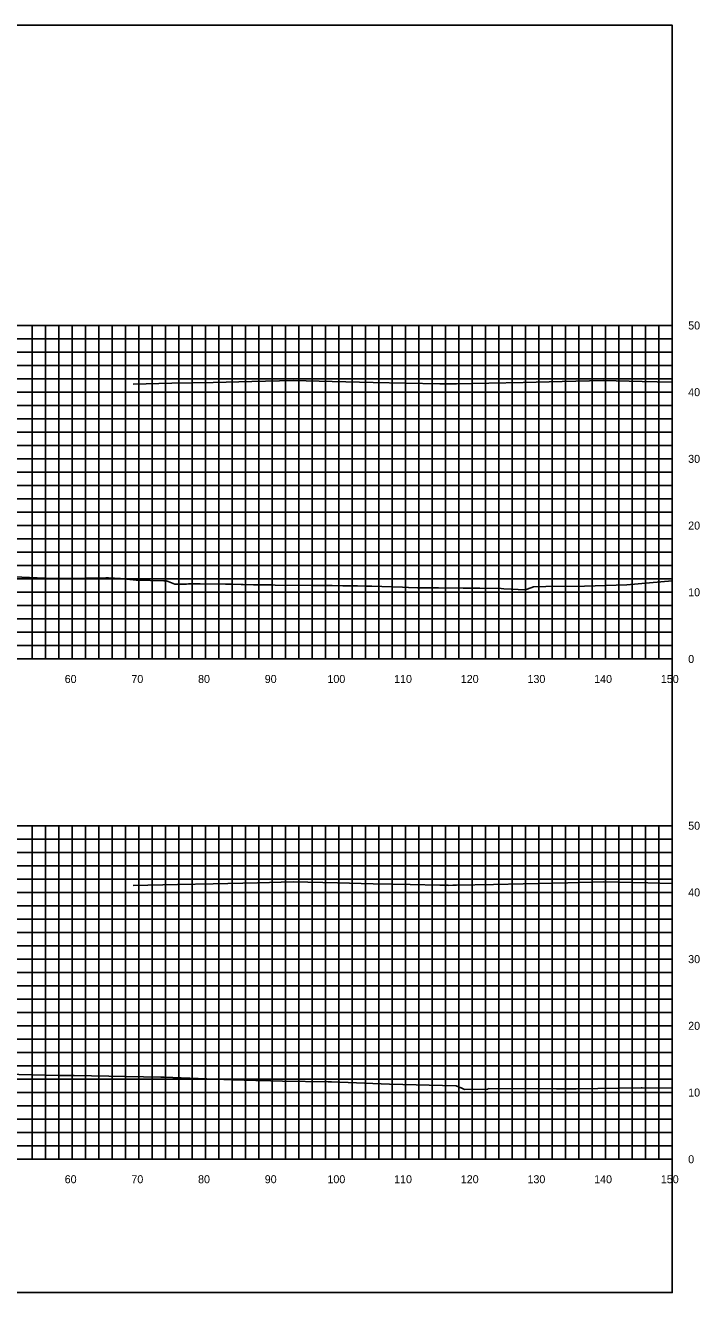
# Model space of a CAD drawing. Extents: x 1797714 to 1804825, y 249015 to 250269.
# Drawn here: x 1802997.2 to 1803098.3, y 249628.2 to 249818.2 of the extents above; entities that cross this region are included whole.
import ezdxf

# ---------------------------------------------------------------- set-up
doc = ezdxf.new("R2010")
doc.units = 0
for name, color, linetype in [('10', 7, 'Continuous'), ('31', 7, 'Continuous'), ('60', 7, 'Continuous'), ('CL-CNST', 7, 'Continuous'), ('Level 62', 7, 'Continuous'), ('M-ROADS', 7, 'Continuous')]:
    doc.layers.add(name, color=color, linetype=linetype)

msp = doc.modelspace()

# ---------------------------------------------------------------- linework, layer by layer
msp.add_lwpolyline([(1802794.16, 249628.17), (1803094.16, 249628.17), (1803094.16, 249818.17), (1802794.16, 249818.17)], close=True)
at = {"layer": '60'}
for p, q in [((1803094.16, 249723.17), (1803094.16, 249773.17)), ((1803094.22, 249773.17), (1803094.16, 249773.17)), ((1803094.22, 249763.17), (1803094.16, 249763.17)), ((1803094.22, 249753.17), (1803094.16, 249753.17)), ((1803094.22, 249743.17), (1803094.16, 249743.17)), ((1803094.22, 249733.17), (1803094.16, 249733.17)), ((1802794.16, 249723.17), (1803094.16, 249723.17)), ((1803004.16, 249723.11), (1803004.16, 249723.17)), ((1803014.16, 249723.11), (1803014.16, 249723.17)), ((1803024.16, 249723.11), (1803024.16, 249723.17)), ((1803034.16, 249723.11), (1803034.16, 249723.17)), ((1803044.16, 249723.11), (1803044.16, 249723.17)), ((1803054.16, 249723.11), (1803054.16, 249723.17)), ((1803064.16, 249723.11), (1803064.16, 249723.17)), ((1803074.16, 249723.11), (1803074.16, 249723.17)), ((1803084.16, 249723.11), (1803084.16, 249723.17)), ((1803094.16, 249723.11), (1803094.16, 249723.17)), ((1803094.22, 249723.17), (1803094.16, 249723.17)), ((1803094.16, 249648.17), (1803094.16, 249698.17)), ((1803094.22, 249698.17), (1803094.16, 249698.17)), ((1803094.22, 249688.17), (1803094.16, 249688.17)), ((1803094.22, 249678.17), (1803094.16, 249678.17)), ((1803094.22, 249668.17), (1803094.16, 249668.17)), ((1803094.22, 249658.17), (1803094.16, 249658.17)), ((1802794.16, 249648.17), (1803094.16, 249648.17)), ((1803004.16, 249648.11), (1803004.16, 249648.17)), ((1803014.16, 249648.11), (1803014.16, 249648.17)), ((1803024.16, 249648.11), (1803024.16, 249648.17)), ((1803034.16, 249648.11), (1803034.16, 249648.17)), ((1803044.16, 249648.11), (1803044.16, 249648.17)), ((1803054.16, 249648.11), (1803054.16, 249648.17)), ((1803064.16, 249648.11), (1803064.16, 249648.17)), ((1803074.16, 249648.11), (1803074.16, 249648.17)), ((1803084.16, 249648.11), (1803084.16, 249648.17)), ((1803094.16, 249648.11), (1803094.16, 249648.17)), ((1803094.22, 249648.17), (1803094.16, 249648.17))]:
    msp.add_line(p, q, dxfattribs=at)
at = {"layer": 'CL-CNST'}
for points in [[(1803013.32, 249764.38), (1803019.14, 249764.51), (1803025.32, 249764.64), (1803031.14, 249764.77), (1803037.32, 249764.91), (1803043.15, 249764.78), (1803049.32, 249764.64), (1803054.18, 249764.54), (1803059.32, 249764.42), (1803059.92, 249764.41), (1803060.57, 249764.4), (1803060.57, 249764.4), (1803060.57, 249764.4), (1803061.18, 249764.41), (1803061.82, 249764.42), (1803066.68, 249764.53), (1803071.82, 249764.64), (1803077.65, 249764.77), (1803083.82, 249764.91), (1803089.66, 249764.78), (1803094.16, 249764.68)], [(1803013.33, 249689.22), (1803019.98, 249689.36), (1803025.33, 249689.48), (1803031.99, 249689.63), (1803037.33, 249689.75), (1803043.99, 249689.6), (1803049.33, 249689.48), (1803054.88, 249689.36), (1803059.33, 249689.26), (1803060.02, 249689.25), (1803060.58, 249689.24), (1803060.58, 249689.23), (1803060.58, 249689.23), (1803061.27, 249689.25), (1803061.83, 249689.26), (1803067.38, 249689.38), (1803071.83, 249689.48), (1803078.5, 249689.63), (1803083.83, 249689.75), (1803090.5, 249689.6), (1803094.16, 249689.52)]]:
    msp.add_lwpolyline(points, dxfattribs=at)
at = {"layer": 'Level 62'}
for p, q in [((1802794.16, 249773.17), (1803094.16, 249773.17)), ((1802998.16, 249723.17), (1802998.16, 249773.17)), ((1803000.16, 249723.17), (1803000.16, 249773.17)), ((1803002.16, 249723.17), (1803002.16, 249773.17)), ((1803004.16, 249723.17), (1803004.16, 249773.17)), ((1803006.16, 249723.17), (1803006.16, 249773.17)), ((1803008.16, 249723.17), (1803008.16, 249773.17)), ((1803010.16, 249723.17), (1803010.16, 249773.17)), ((1803012.16, 249723.17), (1803012.16, 249773.17)), ((1803014.16, 249723.17), (1803014.16, 249773.17)), ((1803016.16, 249723.17), (1803016.16, 249773.17)), ((1803018.16, 249723.17), (1803018.16, 249773.17)), ((1803020.16, 249723.17), (1803020.16, 249773.17)), ((1803022.16, 249723.17), (1803022.16, 249773.17)), ((1803024.16, 249723.17), (1803024.16, 249773.17)), ((1803026.16, 249723.17), (1803026.16, 249773.17)), ((1803028.16, 249723.17), (1803028.16, 249773.17)), ((1803030.16, 249723.17), (1803030.16, 249773.17)), ((1803032.16, 249723.17), (1803032.16, 249773.17)), ((1803034.16, 249723.17), (1803034.16, 249773.17)), ((1803036.16, 249723.17), (1803036.16, 249773.17)), ((1803038.16, 249723.17), (1803038.16, 249773.17)), ((1803040.16, 249723.17), (1803040.16, 249773.17)), ((1803042.16, 249723.17), (1803042.16, 249773.17)), ((1803044.16, 249723.17), (1803044.16, 249773.17)), ((1803046.16, 249723.17), (1803046.16, 249773.17)), ((1803048.16, 249723.17), (1803048.16, 249773.17)), ((1803050.16, 249723.17), (1803050.16, 249773.17)), ((1803052.16, 249723.17), (1803052.16, 249773.17)), ((1803054.16, 249723.17), (1803054.16, 249773.17)), ((1803056.16, 249723.17), (1803056.16, 249773.17)), ((1803058.16, 249723.17), (1803058.16, 249773.17)), ((1803060.16, 249723.17), (1803060.16, 249773.17)), ((1803062.16, 249723.17), (1803062.16, 249773.17)), ((1803064.16, 249723.17), (1803064.16, 249773.17)), ((1803066.16, 249723.17), (1803066.16, 249773.17)), ((1803068.16, 249723.17), (1803068.16, 249773.17)), ((1803070.16, 249723.17), (1803070.16, 249773.17)), ((1803072.16, 249723.17), (1803072.16, 249773.17)), ((1803074.16, 249723.17), (1803074.16, 249773.17)), ((1803076.16, 249723.17), (1803076.16, 249773.17)), ((1803078.16, 249723.17), (1803078.16, 249773.17)), ((1803080.16, 249723.17), (1803080.16, 249773.17)), ((1803082.16, 249723.17), (1803082.16, 249773.17)), ((1803084.16, 249723.17), (1803084.16, 249773.17)), ((1803086.16, 249723.17), (1803086.16, 249773.17)), ((1803088.16, 249723.17), (1803088.16, 249773.17)), ((1803090.16, 249723.17), (1803090.16, 249773.17)), ((1803092.16, 249723.17), (1803092.16, 249773.17)), ((1803094.16, 249723.17), (1803094.16, 249773.17)), ((1802794.16, 249771.17), (1803094.16, 249771.17)), ((1802794.16, 249769.17), (1803094.16, 249769.17)), ((1802794.16, 249767.17), (1803094.16, 249767.17)), ((1802794.16, 249765.17), (1803094.16, 249765.17)), ((1802794.16, 249763.17), (1803094.16, 249763.17)), ((1802794.16, 249761.17), (1803094.16, 249761.17)), ((1802794.16, 249759.17), (1803094.16, 249759.17)), ((1802794.16, 249757.17), (1803094.16, 249757.17)), ((1802794.16, 249755.17), (1803094.16, 249755.17)), ((1802794.16, 249753.17), (1803094.16, 249753.17)), ((1802794.16, 249751.17), (1803094.16, 249751.17)), ((1802794.16, 249749.17), (1803094.16, 249749.17)), ((1802794.16, 249747.17), (1803094.16, 249747.17)), ((1802794.16, 249745.17), (1803094.16, 249745.17)), ((1802794.16, 249743.17), (1803094.16, 249743.17)), ((1802794.16, 249741.17), (1803094.16, 249741.17)), ((1802794.16, 249739.17), (1803094.16, 249739.17)), ((1802794.16, 249737.17), (1803094.16, 249737.17)), ((1802794.16, 249735.17), (1803094.16, 249735.17)), ((1802794.16, 249733.17), (1803094.16, 249733.17)), ((1802794.16, 249731.17), (1803094.16, 249731.17)), ((1802794.16, 249729.17), (1803094.16, 249729.17)), ((1802794.16, 249727.17), (1803094.16, 249727.17)), ((1802794.16, 249725.17), (1803094.16, 249725.17)), ((1802794.16, 249723.17), (1803094.16, 249723.17)), ((1802794.16, 249698.17), (1803094.16, 249698.17)), ((1802998.16, 249648.17), (1802998.16, 249698.17)), ((1803000.16, 249648.17), (1803000.16, 249698.17)), ((1803002.16, 249648.17), (1803002.16, 249698.17)), ((1803004.16, 249648.17), (1803004.16, 249698.17)), ((1803006.16, 249648.17), (1803006.16, 249698.17)), ((1803008.16, 249648.17), (1803008.16, 249698.17)), ((1803010.16, 249648.17), (1803010.16, 249698.17)), ((1803012.16, 249648.17), (1803012.16, 249698.17)), ((1803014.16, 249648.17), (1803014.16, 249698.17)), ((1803016.16, 249648.17), (1803016.16, 249698.17)), ((1803018.16, 249648.17), (1803018.16, 249698.17)), ((1803020.16, 249648.17), (1803020.16, 249698.17)), ((1803022.16, 249648.17), (1803022.16, 249698.17)), ((1803024.16, 249648.17), (1803024.16, 249698.17)), ((1803026.16, 249648.17), (1803026.16, 249698.17)), ((1803028.16, 249648.17), (1803028.16, 249698.17)), ((1803030.16, 249648.17), (1803030.16, 249698.17)), ((1803032.16, 249648.17), (1803032.16, 249698.17)), ((1803034.16, 249648.17), (1803034.16, 249698.17)), ((1803036.16, 249648.17), (1803036.16, 249698.17)), ((1803038.16, 249648.17), (1803038.16, 249698.17)), ((1803040.16, 249648.17), (1803040.16, 249698.17)), ((1803042.16, 249648.17), (1803042.16, 249698.17)), ((1803044.16, 249648.17), (1803044.16, 249698.17)), ((1803046.16, 249648.17), (1803046.16, 249698.17)), ((1803048.16, 249648.17), (1803048.16, 249698.17)), ((1803050.16, 249648.17), (1803050.16, 249698.17)), ((1803052.16, 249648.17), (1803052.16, 249698.17)), ((1803054.16, 249648.17), (1803054.16, 249698.17)), ((1803056.16, 249648.17), (1803056.16, 249698.17)), ((1803058.16, 249648.17), (1803058.16, 249698.17)), ((1803060.16, 249648.17), (1803060.16, 249698.17)), ((1803062.16, 249648.17), (1803062.16, 249698.17)), ((1803064.16, 249648.17), (1803064.16, 249698.17)), ((1803066.16, 249648.17), (1803066.16, 249698.17)), ((1803068.16, 249648.17), (1803068.16, 249698.17)), ((1803070.16, 249648.17), (1803070.16, 249698.17)), ((1803072.16, 249648.17), (1803072.16, 249698.17)), ((1803074.16, 249648.17), (1803074.16, 249698.17)), ((1803076.16, 249648.17), (1803076.16, 249698.17)), ((1803078.16, 249648.17), (1803078.16, 249698.17)), ((1803080.16, 249648.17), (1803080.16, 249698.17)), ((1803082.16, 249648.17), (1803082.16, 249698.17)), ((1803084.16, 249648.17), (1803084.16, 249698.17)), ((1803086.16, 249648.17), (1803086.16, 249698.17)), ((1803088.16, 249648.17), (1803088.16, 249698.17)), ((1803090.16, 249648.17), (1803090.16, 249698.17)), ((1803092.16, 249648.17), (1803092.16, 249698.17)), ((1803094.16, 249648.17), (1803094.16, 249698.17)), ((1802794.16, 249696.17), (1803094.16, 249696.17)), ((1802794.16, 249694.17), (1803094.16, 249694.17)), ((1802794.16, 249692.17), (1803094.16, 249692.17)), ((1802794.16, 249690.17), (1803094.16, 249690.17)), ((1802794.16, 249688.17), (1803094.16, 249688.17)), ((1802794.16, 249686.17), (1803094.16, 249686.17)), ((1802794.16, 249684.17), (1803094.16, 249684.17)), ((1802794.16, 249682.17), (1803094.16, 249682.17)), ((1802794.16, 249680.17), (1803094.16, 249680.17)), ((1802794.16, 249678.17), (1803094.16, 249678.17)), ((1802794.16, 249676.17), (1803094.16, 249676.17)), ((1802794.16, 249674.17), (1803094.16, 249674.17)), ((1802794.16, 249672.17), (1803094.16, 249672.17)), ((1802794.16, 249670.17), (1803094.16, 249670.17)), ((1802794.16, 249668.17), (1803094.16, 249668.17)), ((1802794.16, 249666.17), (1803094.16, 249666.17)), ((1802794.16, 249664.17), (1803094.16, 249664.17)), ((1802794.16, 249662.17), (1803094.16, 249662.17)), ((1802794.16, 249660.17), (1803094.16, 249660.17)), ((1802794.16, 249658.17), (1803094.16, 249658.17)), ((1802794.16, 249656.17), (1803094.16, 249656.17)), ((1802794.16, 249654.17), (1803094.16, 249654.17)), ((1802794.16, 249652.17), (1803094.16, 249652.17)), ((1802794.16, 249650.17), (1803094.16, 249650.17)), ((1802794.16, 249648.17), (1803094.16, 249648.17))]:
    msp.add_line(p, q, dxfattribs=at)
at = {"layer": 'M-ROADS'}
for points in [[(1802987.34, 249735.85), (1803000.09, 249735.31), (1803002.32, 249735.22), (1803002.57, 249735.22), (1803002.57, 249735.22), (1803002.82, 249735.22), (1803003.42, 249735.22), (1803009.24, 249735.33), (1803009.63, 249735.33), (1803011.44, 249735.26), (1803013.8, 249734.99), (1803013.88, 249734.99), (1803017.91, 249734.9), (1803018.04, 249734.9), (1803018.24, 249734.89), (1803018.29, 249734.88), (1803018.44, 249734.84), (1803018.56, 249734.79), (1803019.57, 249734.37), (1803020.62, 249734.39), (1803020.72, 249734.39), (1803020.83, 249734.4), (1803020.97, 249734.4), (1803021.14, 249734.4), (1803021.35, 249734.41), (1803021.63, 249734.42), (1803022.02, 249734.43), (1803022.54, 249734.44), (1803023.26, 249734.46), (1803023.28, 249734.46), (1803023.31, 249734.46), (1803023.32, 249734.46), (1803023.38, 249734.46), (1803027.16, 249734.4), (1803028.06, 249734.38), (1803029.51, 249734.35), (1803029.82, 249734.34), (1803031.35, 249734.31), (1803032.41, 249734.29), (1803033.2, 249734.28), (1803033.51, 249734.28), (1803034.14, 249734.27), (1803034.64, 249734.26), (1803040.01, 249734.21), (1803041.87, 249734.18), (1803042.38, 249734.18), (1803042.79, 249734.17), (1803043.17, 249734.17), (1803044.76, 249734.15), (1803046.5, 249734.13), (1803046.94, 249734.12), (1803046.98, 249734.12), (1803048.28, 249734.09), (1803048.44, 249734.09), (1803049.13, 249734.07), (1803052.12, 249733.97), (1803053.74, 249733.92), (1803054.6, 249733.9), (1803055.96, 249733.86), (1803057.08, 249733.84), (1803059.14, 249733.82), (1803062.84, 249733.81), (1803065.16, 249733.77), (1803065.3, 249733.77), (1803068.52, 249733.74), (1803068.92, 249733.71), (1803072.17, 249733.52), (1803072.42, 249733.62), (1803073.35, 249734.01), (1803075.23, 249734.03), (1803081, 249734.08), (1803087.38, 249734.3), (1803094.16, 249734.87)], [(1802990.02, 249661.03), (1803002.3, 249660.74), (1803002.74, 249660.74), (1803003.22, 249660.74), (1803003.23, 249660.74), (1803003.73, 249660.72), (1803004.49, 249660.7), (1803017.49, 249660.48), (1803017.74, 249660.48), (1803017.99, 249660.48), (1803028.2, 249660.08), (1803031.71, 249659.98), (1803031.84, 249659.98), (1803032.2, 249659.98), (1803035.7, 249659.89), (1803042.57, 249659.79), (1803042.86, 249659.79), (1803043.07, 249659.79), (1803051.76, 249659.44), (1803061.74, 249659.15), (1803061.75, 249659.15), (1803061.77, 249659.15), (1803062.22, 249658.96), (1803062.36, 249658.9), (1803062.53, 249658.85), (1803063.03, 249658.63), (1803066.42, 249658.69), (1803066.52, 249658.69), (1803066.61, 249658.75), (1803076.83, 249658.72), (1803077.17, 249658.72), (1803079.75, 249658.73), (1803089.52, 249658.87), (1803089.68, 249658.87), (1803094.16, 249658.81)]]:
    msp.add_lwpolyline(points, dxfattribs=at)

# ---------------------------------------------------------------- texts
at = {"layer": '10'}
for s, p in [('60', (1803003.06, 249719.57)), ('70', (1803013.06, 249719.57)), ('80', (1803023.06, 249719.57)), ('90', (1803033.06, 249719.57)), ('100', (1803042.46, 249719.57)), ('110', (1803052.46, 249719.57)), ('120', (1803062.46, 249719.57)), ('130', (1803072.46, 249719.57)), ('140', (1803082.46, 249719.57)), ('150', (1803092.46, 249719.57)), ('60', (1803003.06, 249644.57)), ('70', (1803013.06, 249644.57)), ('80', (1803023.06, 249644.57)), ('90', (1803033.06, 249644.57)), ('100', (1803042.46, 249644.57)), ('110', (1803052.46, 249644.57)), ('120', (1803062.46, 249644.57)), ('130', (1803072.46, 249644.57)), ('140', (1803082.46, 249644.57)), ('150', (1803092.46, 249644.57))]:
    msp.add_text(s, height=1.2, dxfattribs=at).set_placement(p)
at = {"layer": '31'}
for s, p in [('50', (1803096.56, 249772.57)), ('40', (1803096.56, 249762.57)), ('30', (1803096.56, 249752.57)), ('20', (1803096.56, 249742.57)), ('10', (1803096.56, 249732.57)), ('0', (1803096.56, 249722.57)), ('50', (1803096.56, 249697.57)), ('40', (1803096.56, 249687.57)), ('30', (1803096.56, 249677.57)), ('20', (1803096.56, 249667.57)), ('10', (1803096.56, 249657.57)), ('0', (1803096.56, 249647.57))]:
    msp.add_text(s, height=1.2, dxfattribs=at).set_placement(p)

doc.saveas('drawing.dxf')
